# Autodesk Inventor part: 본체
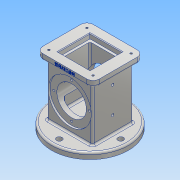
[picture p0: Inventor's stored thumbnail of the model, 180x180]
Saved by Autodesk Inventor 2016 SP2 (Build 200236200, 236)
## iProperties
Created: 2018-10
Part Number: 본체
Material: 알루미늄 6061
Document SubType Name: Modeling
Designer: Administrator
Mass: 984.858 g
Surface Area: 745.107 cm^2
Volume: 364.762 cm^3
Density: 2.7 g/cm^3
Appearance: 알루미늄 - 평지
Author: Administrator
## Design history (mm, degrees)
sketch "스케치1"
  geometry: C1 r 62.5 at (0, 0); 1 further point
  constraints: 1 centre point, 1 coincident
  dimensions: "d0" = 125 diameter of C1
extrude "돌출1" new body sketch "스케치1" distance "d1" = 10; taper "d2" = 0 deg
fillet "모깎기1" dims "d3" = 3
sketch "스케치2"
  geometry: C1 r 59.5 at (0, 0) reference; C2 r 4.5 at (0, 50); C3 r 4.5 at (-50, 0); C4 r 4.5 at (50, 0); C5 r 4.5 at (0, -50); A1 r 50 centre (0, 0) between (0, 50) and (-50, 0)
  constraints: 5 centre point, 4 point on circle, 1 coincident
  dimensions: "d4" = 100 diameter of A1; "d5" = 9 diameter of C3; "d6" = 9 diameter of C2; "d7" = 9 diameter of C5; "d8" = 9 diameter of C4
extrude "돌출2" cut sketch "스케치2" distance "d9" = 10; taper "d10" = 0 deg
sketch "스케치3"
  geometry: L1 (-37, -33)-(37, -33); L2 (37, -33)-(37, 33); L3 (37, 33)-(-37, 33); L4 (-37, 33)-(-37, -33); L5 (-37, -33)-(37, 33); L6 (37, -33)-(-37, 33); C1 r 59.5 at (0, 0) reference
  constraints: 12 end point, 2 midpoint, 2 parallel, 1 horizontal, 1 perpendicular
  dimensions: "d11" = 74 distance of L2.end L3.end; "d12" = 66 distance of L1.end L2.end
extrude "돌출3" join sketch "스케치3" distance "d13" = 88; taper "d14" = 0 deg
sketch "스케치4"
  geometry: L1 (-46, -41)-(46, -41); L2 (46, -41)-(46, 41); L3 (46, 41)-(-46, 41); L4 (-46, 41)-(-46, -41); L5 (-46, -41)-(46, 41); L6 (46, -41)-(-46, 41); 1 further point
  constraints: 12 end point, 2 midpoint, 2 parallel, 1 horizontal, 1 perpendicular
  dimensions: "d15" = 92 distance of L2.end L3.end; "d16" = 82 distance of L1.end L2.end
extrude "돌출4" join sketch "스케치4" distance "d17" = 10; taper "d18" = 0 deg
fillet "모깎기2" dims "d19" = 10
sketch "스케치5"
  geometry: A1 r 10 centre (-36, 31) between (-36, 41) and (-46, 31) reference; A2 r 10 centre (-36, -31) between (-46, -31) and (-36, -41) reference; A3 r 10 centre (36, -31) between (36, -41) and (46, -31) reference; A4 r 10 centre (36, 31) between (46, 31) and (36, 41) reference; 1 further point
hole "구멍1" sketch "스케치5" at (-36, 31), (36, 31), (36, -31), (-36, -31) diameter "d20" = 3.242; stored, may be unused: countersink angle "d24" = 90 deg, drill point angle "d26" = 118 deg; dims "d21" = 4, "d22" = 4, "d23" = 2, "d25" = 6
sketch "스케치6"
  geometry: L1 (37, -10)-(37, 44); C1 r 35 at (37, 44)
  constraints: 2 end point, 1 centre point, 1 coincident, 1 vertical
  dimensions: "d27" = 54 distance of L1.start L1.end; "d28" = 70 diameter of C1
extrude "돌출5" cut sketch "스케치6" distance "d29" = 3; taper "d30" = 0 deg
sketch "스케치7"
  geometry: C1 r 35 at (0, 0) reference; C2 r 24 at (0, 0); 1 further point
  constraints: 1 centre point, 1 coincident
  dimensions: "d31" = 48 diameter of C2
extrude "돌출6" cut sketch "스케치7" distance "d32" = 8; taper "d33" = 0 deg
sketch "스케치8" dims "d34" = 58
  geometry: C1 r 35 at (0, 0) reference; 3 further points
  constraints: 1 coincident, 1 vertical alignment, 2 other
hole "구멍2" sketch "스케치8" at (0, 29) diameter "d35" = 3.242; stored, may be unused: countersink angle "d39" = 90 deg, drill point angle "d41" = 118 deg; dims "d36" = 4, "d37" = 4, "d38" = 2, "d40" = 6
fillet "모깎기3" dims "d45" = 3
fillet "모깎기4" dims "d46" = 3
fillet "모깎기5" dims "d47" = 3
fillet "모깎기6" dims "d48" = 3
sketch "스케치9"
  geometry: L1 (-26, -26)-(26, -26); L2 (26, -26)-(26, 26); L3 (26, 26)-(-26, 26); L4 (-26, 26)-(-26, -26); L5 (-26, -26)-(26, 26); L6 (26, -26)-(-26, 26); 1 further point
  constraints: 12 end point, 2 midpoint, 2 parallel, 1 horizontal, 1 perpendicular
  dimensions: "d49" = 52 distance of L2.end L3.end; "d50" = 52 distance of L1.end L2.end
extrude "돌출7" cut sketch "스케치9" distance "d51" = 8; taper "d52" = 0 deg
sketch "스케치10"
  geometry: L1 (-22, -22)-(22, -22); L2 (22, -22)-(22, 22); L3 (22, 22)-(-22, 22); L4 (-22, 22)-(-22, -22); L5 (-22, -22)-(22, 22); L6 (22, -22)-(-22, 22); 1 further point
  constraints: 12 end point, 2 midpoint, 2 parallel, 1 horizontal, 1 perpendicular
  dimensions: "d53" = 44 distance of L2.end L3.end; "d54" = 44 distance of L1.end L2.end
extrude "돌출8" cut sketch "스케치10" distance "d55" = 74; taper "d56" = 0 deg
sketch "스케치11"
  geometry: C1 r 24 at (0, 0); A1 r 24 centre (0, 0) between (22, -9.592) and (22, 9.592) reference; 1 further point
  constraints: 1 centre point, 1 coincident
extrude "돌출9" cut sketch "스케치11" distance "d57" = 74; taper "d58" = 0 deg
sketch "스케치13"
  geometry: L1 (0, 0)-(-28, 0); L2 (-62.5, 0)-(62.5, 0) reference; L3 (-28, 0)-(-24.826, 18); L4 (-24.826, 18)-(0, 18); L5 (30, 13)-(-30, 13) reference; L6 (0, 18)-(0, 0)
  constraints: 8 end point, 1 parallel, 1 perpendicular, 1 point on line
  dimensions: "d59" = 28 distance of L1.start L1.end; "d60" = 80 deg angle of L1 L3; "d61" = 18 distance between parallel lines of L1 L4
revolve "회전1" sketch "스케치13" stored, may be unused: angle "d62" = 90 deg
fillet "모깎기7" dims "d63" = 3
fillet "모깎기8" dims "d64" = 3
fillet "모깎기9" dims "d65" = 3
sketch "스케치14"
  geometry: L1 (95, 30)-(58, 30); L2 (50.592, 49)-(50.592, 11) reference; L3 (58, 30)-(15, 30)
  constraints: 4 end point, 1 horizontal, 1 perpendicular
  dimensions: "d66" = 37 distance of L1.start L1.end; "d68" = 43 distance of L1.end L3.end
hole "구멍3" sketch "스케치14" at (15, 30), (58, 30) diameter "d69" = 4.134; stored, may be unused: countersink angle "d73" = 90 deg, drill point angle "d75" = 118 deg; dims "d70" = 20, "d71" = 4, "d72" = 2, "d74" = 21
node "작업 평면1"
sketch "스케치15"
  geometry: L1 (72, 0)-(82, 0) reference; L2 (-10, 0)-(-10, -7) reference; 2 further points
  constraints: 1 other
  dimensions: "d77" = 4 distance from line of L1 point (36, -4); "d78" = 46 distance from line of L2 point (36, -4)
feature "엠보싱1" sketch "스케치15" dims "d79" = 0.5, "d80" = 0
chamfer "모따기1" distance "d81" = 1; stored, may be unused: second distance "d82" = 2, angle "d83" = 45 deg
node "솔리드1"
mirror "대칭1"
pattern_circular "원형 패턴1" dims angle "d43" = 360 deg
mirror "대칭2"
other parameters: "d76" = 12.5
